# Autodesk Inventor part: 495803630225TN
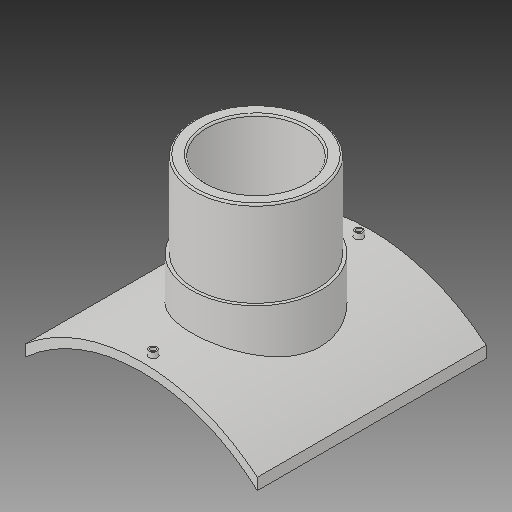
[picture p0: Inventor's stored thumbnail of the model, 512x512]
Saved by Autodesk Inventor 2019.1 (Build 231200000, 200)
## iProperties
Created: 2017-10
Part Number: 495803630225TN
Material: Generic
Description: PLASSON BRANCH SADDLE  630x225
Document SubType Name: Modeling
Designer: KIM
Mass: 2754.05 g
Surface Area: 3037.44 cm^2
Volume: 2754.05 cm^3
Density: 1 g/cm^3
Appearance: Default
Author: KIM
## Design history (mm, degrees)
derived "495803.ipt"
feature "Solid1::495803.ipt"
tag "TaggingFeature1"
body "Solid1"
other parameters: "d1" = 16, "d2" = 425, "d4" = 0, "d12" = 340.6, "d13" = 14, "d14" = 189, "d16" = 5 deg, "d18" = 4, "d19" = 14, "d20" = 0, "d21" = 3, "d22" = 0, "d23" = 556, "d24" = 236.25, "d25" = 16, "d28" = 0, "d29" = 9.6, "d31" = 0, "d32" = 112.5, "d33" = 0, "d34" = 6.3, "d36" = 225, "d37" = 157.5, "d38" = 0, "d39" = 3.15, "d_1" = 225, "B_" = 425, "H_" = 225, "x_" = 16, "D_" = 16
